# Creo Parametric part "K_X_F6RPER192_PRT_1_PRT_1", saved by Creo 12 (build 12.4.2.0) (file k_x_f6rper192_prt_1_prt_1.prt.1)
Units: Custom; MM, KILOGRAM, SECS

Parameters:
  PTC_WM_ITERATION = "0"
  PTC_WM_VERSION = "-.0"
  PTC_WM_LIFECYCLE_STATE = "In Work"
  PTC_WM_LIFECYCLE = "MO_CADDocument"
  PTC_WM_CREATED_BY = "Maximilian Roepper (Z0017RMS: MO)"
  PTC_WM_CREATED_ON = "18-Sep-26 11:36:42 AM"
  PTC_WM_MODIFIED_BY = "Maximilian Roepper (Z0017RMS: MO)"
  PTC_WM_MODIFIED_ON = "18-Sep-26 11:36:46 AM"
  PDMLINKNUMBER = "PDM000071455228"
  PTC_WM_NAME = "k_x_f6rper192_prt_1_prt_1.prt"
  PTC_WM_NUMBER = "PDM000071455228"

Other parameters: WEIGHT, WEIGHT_FACTOR, WEIGHT_ADD, _MASS_TEMP, _DIFF_TEMP, MC_ERRORS, SUPPLIER

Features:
  1. coordinate system
  2. datum plane "PRT_YZ"
  3. datum plane "PRT_XY"
  4. datum plane "PRT_XZ"
  5. coordinate system
  6. datum axis
  7. datum axis
  8. datum axis
  9. coordinate system
  10. imported feature
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
Other named items: PRT, SIEMENS_MO, DRW_VIEW_ORG, PRT_X, PRT_Y, PRT_Z, CS0, ROUGH_GROB

Layers: 00_STD_CSYS-KSYS, 01_STD_PLANES-EBENEN, 02_STD_AXES-ACHSEN, 03_STD_CSYS-KSYS, 24_IMPORT_FEAT-IMPORT_KE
